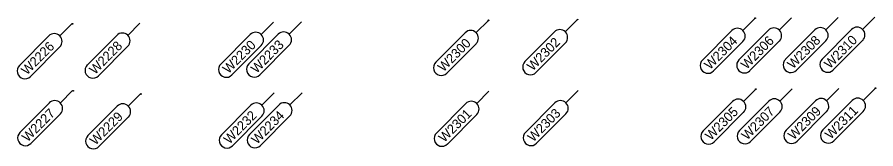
# Model space of a CAD drawing. Extents: x 12479652 to 12487250, y 9842710 to 9846560.
# Drawn here: x 12483761.4 to 12483875, y 9842836.7 to 9842854.1 of the extents above; entities that cross this region are included whole.
import ezdxf

# ---------------------------------------------------------------- set-up
doc = ezdxf.new("R2010")
doc.units = 0
doc.layers.add('_CIVIL_CONSTRUCTION', color=7, linetype='Continuous')
doc.layers.add('TextAlignmentLrg', color=7, linetype='Continuous')

msp = doc.modelspace()

# ---------------------------------------------------------------- linework, layer by layer
at = {"layer": '_CIVIL_CONSTRUCTION'}
for p, q in [((12483874.89, 9842854.13), (12483873.27, 9842852.5)), ((12483768.66, 9842853.28), (12483767.04, 9842851.65)), ((12483777.65, 9842853.36), (12483776.03, 9842851.72)), ((12483795.32, 9842853.47), (12483793.69, 9842851.84)), ((12483799.01, 9842853.5), (12483797.39, 9842851.87)), ((12483823.76, 9842853.71), (12483822.14, 9842852.08)), ((12483835.56, 9842853.81), (12483833.93, 9842852.17)), ((12483859.05, 9842854), (12483857.43, 9842852.37)), ((12483863.87, 9842854.04), (12483862.25, 9842852.41)), ((12483870.04, 9842854.09), (12483868.41, 9842852.46)), ((12483792.05, 9842847.95), (12483795.94, 9842851.87)), ((12483816.8, 9842848.16), (12483820.69, 9842852.07)), ((12483828.59, 9842848.26), (12483832.48, 9842852.17)), ((12483852.09, 9842848.45), (12483855.98, 9842852.37)), ((12483856.91, 9842848.49), (12483860.8, 9842852.41)), ((12483863.07, 9842848.55), (12483866.96, 9842852.46)), ((12483867.93, 9842848.59), (12483871.82, 9842852.5)), ((12483761.7, 9842847.73), (12483765.58, 9842851.64)), ((12483770.69, 9842847.81), (12483774.58, 9842851.72)), ((12483788.35, 9842847.92), (12483792.24, 9842851.83)), ((12483833.94, 9842850.72), (12483830.05, 9842846.81)), ((12483857.44, 9842850.92), (12483853.55, 9842847.01)), ((12483862.25, 9842850.96), (12483858.36, 9842847.05)), ((12483868.42, 9842851.01), (12483864.53, 9842847.1)), ((12483873.28, 9842851.05), (12483869.39, 9842847.14)), ((12483767.04, 9842850.2), (12483763.15, 9842846.29)), ((12483776.03, 9842850.27), (12483772.14, 9842846.36)), ((12483793.7, 9842850.39), (12483789.81, 9842846.48)), ((12483797.4, 9842850.42), (12483793.51, 9842846.51)), ((12483822.14, 9842850.62), (12483818.25, 9842846.71)), ((12483768.73, 9842844.41), (12483767.11, 9842842.78)), ((12483777.72, 9842843.99), (12483776.1, 9842842.36)), ((12483795.39, 9842844.1), (12483793.77, 9842842.47)), ((12483799.09, 9842844.13), (12483797.47, 9842842.5)), ((12483823.83, 9842844.33), (12483822.21, 9842842.7)), ((12483835.63, 9842844.42), (12483834.01, 9842842.79)), ((12483859.13, 9842844.61), (12483857.51, 9842842.98)), ((12483863.95, 9842844.65), (12483862.33, 9842843.02)), ((12483870.11, 9842844.7), (12483868.49, 9842843.07)), ((12483874.97, 9842844.74), (12483873.35, 9842843.11)), ((12483761.77, 9842838.86), (12483765.66, 9842842.78)), ((12483828.67, 9842838.87), (12483832.56, 9842842.79)), ((12483852.17, 9842839.06), (12483856.06, 9842842.98)), ((12483856.99, 9842839.1), (12483860.87, 9842843.02)), ((12483863.15, 9842839.15), (12483867.04, 9842843.07)), ((12483868.01, 9842839.19), (12483871.9, 9842843.1)), ((12483770.76, 9842838.44), (12483774.65, 9842842.35)), ((12483788.43, 9842838.55), (12483792.32, 9842842.46)), ((12483792.13, 9842838.58), (12483796.02, 9842842.49)), ((12483816.87, 9842838.78), (12483820.76, 9842842.69)), ((12483868.49, 9842841.62), (12483864.6, 9842837.71)), ((12483873.35, 9842841.66), (12483869.46, 9842837.75)), ((12483767.11, 9842841.33), (12483763.22, 9842837.42)), ((12483776.11, 9842840.91), (12483772.22, 9842836.99)), ((12483793.77, 9842841.02), (12483789.88, 9842837.1)), ((12483797.47, 9842841.05), (12483793.58, 9842837.13)), ((12483822.22, 9842841.24), (12483818.33, 9842837.33)), ((12483834.01, 9842841.34), (12483830.13, 9842837.43)), ((12483857.51, 9842841.53), (12483853.62, 9842837.62)), ((12483862.33, 9842841.57), (12483858.44, 9842837.66))]:
    msp.add_line(p, q, dxfattribs=at)
for centre, start, end in [((12483766.31, 9842850.92), 315.1702, 135.1702), ((12483775.3, 9842851), 315.1702, 135.1702), ((12483792.97, 9842851.11), 315.1702, 135.1702), ((12483796.67, 9842851.14), 315.1702, 135.1702), ((12483821.41, 9842851.35), 315.1702, 135.1702), ((12483833.21, 9842851.45), 315.1702, 135.1702), ((12483856.71, 9842851.64), 315.1702, 135.1702), ((12483861.53, 9842851.68), 315.1702, 135.1702), ((12483867.69, 9842851.73), 315.1702, 135.1702), ((12483872.55, 9842851.78), 315.1702, 135.1702), ((12483852.82, 9842847.73), 135.1702, 315.1702), ((12483857.64, 9842847.77), 135.1702, 315.1702), ((12483863.8, 9842847.82), 135.1702, 315.1702), ((12483868.66, 9842847.86), 135.1702, 315.1702), ((12483762.42, 9842847.01), 135.1702, 315.1702), ((12483771.41, 9842847.08), 135.1702, 315.1702), ((12483789.08, 9842847.2), 135.1702, 315.1702), ((12483792.78, 9842847.23), 135.1702, 315.1702), ((12483817.52, 9842847.43), 135.1702, 315.1702), ((12483829.32, 9842847.53), 135.1702, 315.1702), ((12483766.38, 9842842.05), 315.1702, 135.1702), ((12483793.05, 9842841.74), 315.1702, 135.1702), ((12483796.74, 9842841.77), 315.1702, 135.1702), ((12483821.49, 9842841.97), 315.1702, 135.1702), ((12483833.29, 9842842.06), 315.1702, 135.1702), ((12483856.79, 9842842.25), 315.1702, 135.1702), ((12483861.6, 9842842.29), 315.1702, 135.1702), ((12483867.77, 9842842.34), 315.1702, 135.1702), ((12483872.63, 9842842.38), 315.1702, 135.1702), ((12483775.38, 9842841.63), 315.1702, 135.1702), ((12483762.49, 9842838.14), 135.1702, 315.1702), ((12483771.49, 9842837.72), 135.1702, 315.1702), ((12483789.16, 9842837.83), 135.1702, 315.1702), ((12483792.85, 9842837.86), 135.1702, 315.1702), ((12483817.6, 9842838.06), 135.1702, 315.1702), ((12483829.4, 9842838.15), 135.1702, 315.1702), ((12483852.9, 9842838.34), 135.1702, 315.1702), ((12483857.71, 9842838.38), 135.1702, 315.1702), ((12483863.88, 9842838.43), 135.1702, 315.1702), ((12483868.74, 9842838.47), 135.1702, 315.1702)]:
    msp.add_arc(centre, 1.03, start, end, dxfattribs=at)
at = {"layer": 'TextAlignmentLrg'}
for centre in [(12483768.72, 9842853.25), (12483823.76, 9842853.71), (12483835.56, 9842853.81), (12483859.06, 9842854), (12483768.8, 9842844.38), (12483777.79, 9842843.96), (12483859.13, 9842844.61), (12483874.97, 9842844.74)]:
    msp.add_circle(centre, 0.05, dxfattribs=at)

# ---------------------------------------------------------------- texts
at = {"layer": '_CIVIL_CONSTRUCTION'}
for s, p in [('W2226', (12483762.69, 9842846.38)), ('W2228', (12483771.69, 9842846.46)), ('W2230', (12483789.35, 9842846.57)), ('W2233', (12483793.06, 9842846.61)), ('W2300', (12483817.8, 9842846.81)), ('W2302', (12483829.61, 9842846.93)), ('W2304', (12483853.08, 9842847.1)), ('W2306', (12483857.91, 9842847.14)), ('W2308', (12483864.07, 9842847.19)), ('W2310', (12483868.93, 9842847.23)), ('W2227', (12483762.78, 9842837.52)), ('W2232', (12483789.47, 9842837.24)), ('W2234', (12483793.12, 9842837.22)), ('W2301', (12483817.91, 9842837.46)), ('W2303', (12483829.68, 9842837.53)), ('W2305', (12483853.18, 9842837.73)), ('W2307', (12483858, 9842837.76)), ('W2309', (12483864.15, 9842837.8)), ('W2311', (12483869.04, 9842837.88)), ('W2229', (12483771.76, 9842837.09))]:
    msp.add_text(s, height=1.25, rotation=45.1702, dxfattribs=at).set_placement(p)

doc.saveas('drawing.dxf')
